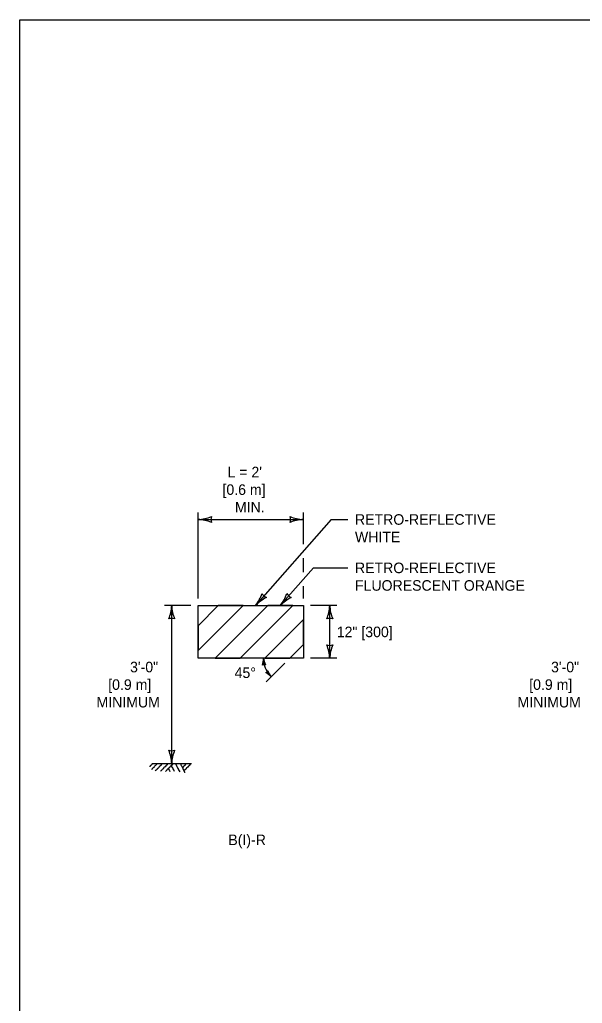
# Model space of a CAD drawing. Extents: x 49991.4 to 50021, y 49987.6 to 50011.4.
# Drawn here: x 49999.38 to 50002.59, y 49993.4 to 49999 of the extents above; entities that cross this region are included whole.
import ezdxf

# ---------------------------------------------------------------- set-up
doc = ezdxf.new("R2010")
doc.units = 0
for name, color, linetype in [('Level 1', 7, 'Continuous'), ('Level 2', 7, 'Continuous'), ('Level 3', 7, 'Continuous')]:
    doc.layers.add(name, color=color, linetype=linetype)

msp = doc.modelspace()

# ---------------------------------------------------------------- linework, layer by layer
at = {"layer": 'Level 1'}
for p, q in [((50000.3991, 49995.5483), (50000.5142, 49995.6636)), ((50000.3991, 49995.4068), (50000.6555, 49995.6636)), ((50000.5142, 49995.6636), (50000.3991, 49995.5483)), ((50000.3991, 49995.4068), (50000.6555, 49995.6636)), ((50000.4973, 49995.3636), (50000.7968, 49995.6636)), ((50000.7968, 49995.6636), (50000.4973, 49995.3636)), ((50000.6387, 49995.3636), (50000.9381, 49995.6636)), ((50000.6387, 49995.3636), (50000.9381, 49995.6636)), ((50000.7798, 49995.3636), (50000.9991, 49995.5833)), ((50000.9991, 49995.5833), (50000.7798, 49995.3636)), ((50000.9212, 49995.3636), (50000.9991, 49995.4416)), ((50000.9212, 49995.3636), (50000.9991, 49995.4416))]:
    msp.add_line(p, q, dxfattribs=at)
for points in [[(49999.3835, 49998.9992), (50016.7501, 49998.9992), (50016.7501, 49987.7988), (49999.3835, 49987.7988)], [(50000.3991, 49995.6636), (50000.9991, 49995.6636), (50000.9991, 49995.3636), (50000.3991, 49995.3636)]]:
    msp.add_lwpolyline(points, close=True, dxfattribs=at)
for points in [[(50000.6555, 49995.6636), (50000.5142, 49995.6636)], [(50000.9381, 49995.6636), (50000.7968, 49995.6636)], [(50000.9991, 49995.4416), (50000.9991, 49995.5833)], [(50000.3991, 49995.5483), (50000.3991, 49995.4068)], [(50000.4973, 49995.3636), (50000.6387, 49995.3636)], [(50000.7798, 49995.3636), (50000.9212, 49995.3636)], [(50000.1386, 49994.7636), (50000.1384, 49994.761), (50000.1352, 49994.7583), (50000.1351, 49994.7568), (50000.1336, 49994.757), (50000.1319, 49994.7542), (50000.1305, 49994.7543), (50000.1303, 49994.7528), (50000.1272, 49994.7502), (50000.1271, 49994.7488), (50000.1256, 49994.7489), (50000.124, 49994.7462)], [(50000.1688, 49994.7636), (50000.1599, 49994.7562), (50000.1598, 49994.7547), (50000.1584, 49994.7548), (50000.1567, 49994.7521), (50000.1537, 49994.7508), (50000.1518, 49994.7467), (50000.1488, 49994.7454), (50000.1487, 49994.744), (50000.1455, 49994.7413), (50000.1454, 49994.7398), (50000.1439, 49994.7399), (50000.1422, 49994.7372), (50000.1408, 49994.7373), (50000.1406, 49994.7359), (50000.1375, 49994.7332), (50000.1374, 49994.7317), (50000.1359, 49994.7319), (50000.1342, 49994.729)], [(50000.1959, 49994.7636), (50000.1897, 49994.7566), (50000.1896, 49994.7551), (50000.1881, 49994.7552), (50000.1864, 49994.7524), (50000.1817, 49994.7484), (50000.1815, 49994.747), (50000.18, 49994.7472), (50000.1783, 49994.7444), (50000.1754, 49994.7431), (50000.1735, 49994.7389), (50000.1705, 49994.7376), (50000.1704, 49994.7362), (50000.1671, 49994.7336), (50000.167, 49994.7321), (50000.1656, 49994.7322), (50000.1639, 49994.7295), (50000.1625, 49994.7296), (50000.1623, 49994.7281), (50000.1592, 49994.7255), (50000.1591, 49994.724), (50000.1576, 49994.7241), (50000.1558, 49994.7213)], [(50000.2274, 49994.7636), (50000.2192, 49994.7544), (50000.2191, 49994.7529), (50000.2176, 49994.7531), (50000.2158, 49994.7503), (50000.2112, 49994.7463), (50000.2111, 49994.7449), (50000.2096, 49994.745), (50000.2079, 49994.7421), (50000.2048, 49994.741), (50000.203, 49994.7367), (50000.2, 49994.7355), (50000.1999, 49994.7341), (50000.1967, 49994.7315), (50000.1965, 49994.73), (50000.1951, 49994.7301), (50000.1934, 49994.7273), (50000.1919, 49994.7275), (50000.1918, 49994.726), (50000.1886, 49994.7233), (50000.1885, 49994.7218), (50000.1871, 49994.722), (50000.1854, 49994.7192)], [(50000.2561, 49994.7636), (50000.2474, 49994.7538), (50000.2472, 49994.7524), (50000.2457, 49994.7525), (50000.2441, 49994.7497), (50000.2393, 49994.7457), (50000.2392, 49994.7443), (50000.2377, 49994.7444), (50000.2361, 49994.7416), (50000.2331, 49994.7404), (50000.2312, 49994.7361), (50000.2281, 49994.7349), (50000.228, 49994.7335), (50000.2248, 49994.7309), (50000.2247, 49994.7294), (50000.2233, 49994.7295), (50000.2215, 49994.7267), (50000.2202, 49994.7268), (50000.22, 49994.7254), (50000.2168, 49994.7227), (50000.2167, 49994.7213), (50000.2153, 49994.7214), (50000.2135, 49994.7186)], [(50000.2305, 49994.7376), (50000.234, 49994.7271), (50000.2369, 49994.7254), (50000.2393, 49994.7194)], [(50000.247, 49994.7538), (50000.2505, 49994.7433), (50000.2532, 49994.7416), (50000.2581, 49994.7294), (50000.2595, 49994.7293), (50000.2608, 49994.7263), (50000.2606, 49994.7248), (50000.2633, 49994.7216), (50000.2636, 49994.7209)], [(50000.2715, 49994.7636), (50000.2761, 49994.7502), (50000.2788, 49994.7485), (50000.2836, 49994.7363), (50000.2851, 49994.7362), (50000.2862, 49994.7333), (50000.2861, 49994.7318), (50000.2888, 49994.7287), (50000.2911, 49994.7226), (50000.2926, 49994.7224), (50000.2952, 49994.7161)], [(50000.299, 49994.7636), (50000.3026, 49994.7527), (50000.3053, 49994.751), (50000.3102, 49994.7389), (50000.3117, 49994.7388), (50000.3129, 49994.7357), (50000.3127, 49994.7342), (50000.3154, 49994.7311), (50000.3179, 49994.725), (50000.3192, 49994.7249), (50000.3229, 49994.7158), (50000.3258, 49994.7156)], [(50000.333, 49994.7636), (50000.3268, 49994.7565), (50000.3267, 49994.755), (50000.3252, 49994.7552), (50000.3235, 49994.7524), (50000.3187, 49994.7484), (50000.3185, 49994.747), (50000.3171, 49994.7471), (50000.3154, 49994.7443), (50000.3124, 49994.7431), (50000.3117, 49994.7415)], [(50000.3585, 49994.7636), (50000.3484, 49994.7525), (50000.3483, 49994.751), (50000.3468, 49994.7511), (50000.3452, 49994.7483), (50000.3404, 49994.7444), (50000.3403, 49994.7429), (50000.3388, 49994.7431), (50000.3371, 49994.7403), (50000.3341, 49994.739), (50000.3322, 49994.7348), (50000.3291, 49994.7336), (50000.329, 49994.7321), (50000.3259, 49994.7294), (50000.3257, 49994.728), (50000.3243, 49994.7281), (50000.3226, 49994.7254), (50000.3212, 49994.7255), (50000.3212, 49994.7251)]]:
    msp.add_lwpolyline(points, dxfattribs=at)
at = {"layer": 'Level 2'}
msp.add_line((50000.137, 49994.7636), (50000.3611, 49994.7636), dxfattribs=at)
at = {"layer": 'Level 3'}
for p, q in [((50000.3991, 49995.7036), (50000.3991, 49996.1936)), ((50000.9991, 49996.0134), (50000.9991, 49996.1936)), ((50000.3991, 49996.1536), (50000.9991, 49996.1536)), ((50001.1578, 49996.1536), (50000.7262, 49995.6636)), ((50001.1578, 49996.1536), (50001.2528, 49996.1536)), ((50000.9991, 49995.8531), (50000.9991, 49995.9334)), ((50001.0563, 49995.8781), (50000.8674, 49995.6636)), ((50001.0563, 49995.8781), (50001.2528, 49995.8781)), ((50000.9991, 49995.7036), (50000.9991, 49995.7731)), ((50000.3591, 49995.6636), (50000.2091, 49995.6636)), ((50000.2491, 49994.7636), (50000.2491, 49995.6636)), ((50001.1891, 49995.6636), (50001.0391, 49995.6636)), ((50001.1491, 49995.3636), (50001.1491, 49995.6636)), ((50001.1891, 49995.3636), (50001.0391, 49995.3636)), ((50000.8929, 49995.3353), (50000.7867, 49995.2294))]:
    msp.add_line(p, q, dxfattribs=at)
for centre, radius, start, end in [((50000.3876, 49996.3863), 0.233, 272.8273, 292.0772), ((50000.39, 49995.9314), 0.2223, 67.456, 87.6395), ((50000.5273, 49996.1536), 0.0548, 162.1388, 197.8612), ((50001.0083, 49996.3757), 0.2223, 247.456, 267.6395), ((50000.8709, 49996.1536), 0.0548, 342.1388, 17.8612), ((50001.0106, 49995.9208), 0.233, 92.8273, 112.0772), ((50000.544, 49995.8088), 0.233, 321.4511, 340.7009), ((50000.811, 49995.7598), 0.0548, 210.7626, 246.485), ((50000.6852, 49995.8087), 0.233, 321.454, 340.7038), ((50000.9522, 49995.7598), 0.0548, 210.7655, 246.4879), ((50000.8868, 49995.5099), 0.2223, 116.0798, 136.2633), ((50001.0281, 49995.5099), 0.2223, 116.0827, 136.2662), ((50000.027, 49995.6727), 0.2223, 337.456, 357.6395), ((50000.4818, 49995.675), 0.233, 182.8273, 202.0772), ((50000.927, 49995.6727), 0.2223, 337.456, 357.6395), ((50001.3818, 49995.675), 0.233, 182.8273, 202.0772), ((50000.2491, 49995.5353), 0.0548, 72.1388, 107.8612), ((50001.1491, 49995.5353), 0.0548, 72.1388, 107.8612), ((50001.1491, 49995.4918), 0.0548, 252.1388, 287.8612), ((50000.9164, 49995.3521), 0.233, 2.8273, 22.0772), ((50001.3712, 49995.3544), 0.2223, 157.456, 177.6395), ((50000.6602, 49995.3577), 0.1112, 342.8326, 3.0161), ((50000.8865, 49995.3802), 0.1165, 188.2039, 207.4537), ((50000.9212, 49995.3636), 0.15, 182.8308, 219.8549), ((50000.7772, 49995.2997), 0.0274, 77.5154, 113.2378), ((50000.7746, 49995.3074), 0.0274, 291.2236, 326.946), ((50000.7283, 49995.1798), 0.1165, 41.9121, 61.162), ((50000.9041, 49995.3241), 0.1112, 196.5408, 216.7243), ((50000.2491, 49994.8918), 0.0548, 252.1388, 287.8612), ((50000.0164, 49994.7521), 0.233, 2.8273, 22.0772), ((50000.4712, 49994.7544), 0.2223, 157.456, 177.6395)]:
    msp.add_arc(centre, radius, start, end, dxfattribs=at)

# ---------------------------------------------------------------- texts
at = {"layer": 'Level 2'}
for s, p in [("L = 2'", (50000.5672, 49996.3936)), ('[0.6 m]', (50000.5384, 49996.2936)), ('MIN.', (50000.6093, 49996.1936)), ('RETRO-REFLECTIVE', (50001.2928, 49996.1236)), ('WHITE', (50001.2928, 49996.0236)), ('RETRO-REFLECTIVE', (50001.2928, 49995.8481)), ('FLUORESCENT ORANGE', (50001.2928, 49995.7481)), ('12" [300]', (50001.1891, 49995.4836)), ('3\'-0"', (50000.0122, 49995.2836)), ('3\'-0"', (50002.4094, 49995.2836)), ('45°', (50000.6075, 49995.2511)), ('[0.9 m]', (49999.8877, 49995.1836)), ('[0.9 m]', (50002.285, 49995.1836)), ('MINIMUM', (49999.821, 49995.0836)), ('MINIMUM', (50002.2183, 49995.0836)), ('B(I)-R', (50000.5717, 49994.2997))]:
    msp.add_text(s, height=0.06, dxfattribs=at).set_placement(p)

doc.saveas('drawing.dxf')
